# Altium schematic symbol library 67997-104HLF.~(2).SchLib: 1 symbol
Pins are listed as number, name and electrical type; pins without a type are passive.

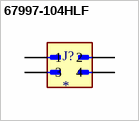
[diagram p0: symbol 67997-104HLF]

## 67997-104HLF
designator J?
BergStikÂ®, Board to Board connector, Unshrouded vertical header, Through Hole, Double Row, 4 Positions, 2.54 mm (0.100in) Pitch; MF: Amphenol ICC; MP: 67997-104HLF
footprint AMPHENOL_67997-104HLF
pins: 1, 2, 3, 4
